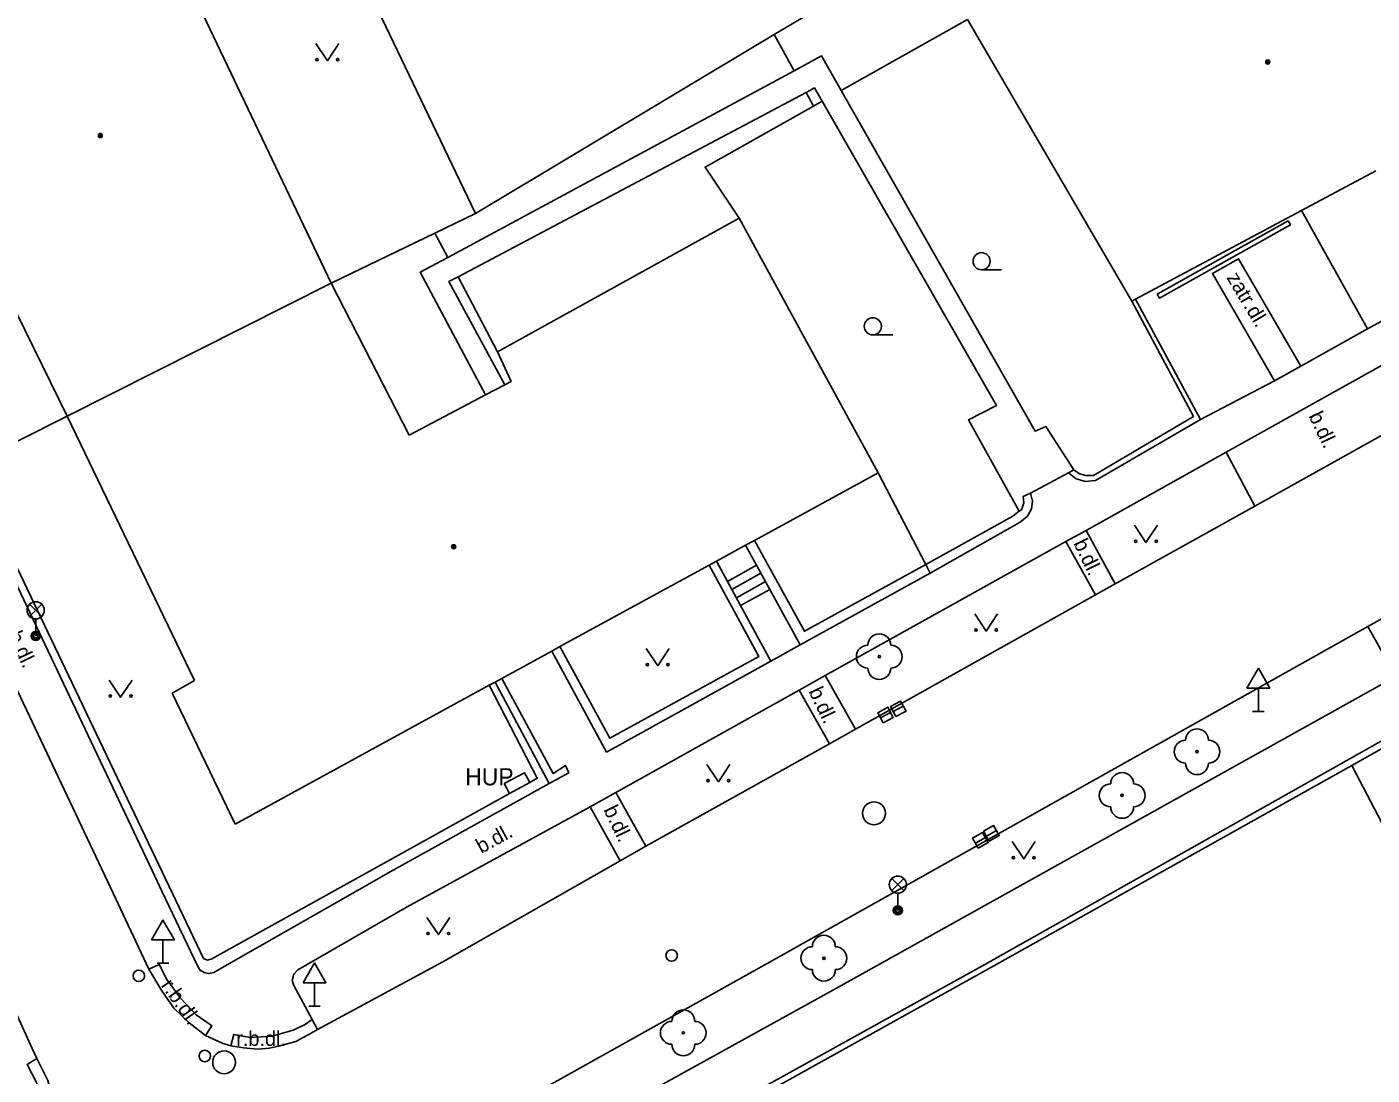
# Model space of a CAD drawing. Extents: x -600391 to -599491, y -1160176 to -1159402.
# Drawn here: x -600164 to -600105.3, y -1159825.7 to -1159779.9 of the extents above; entities that cross this region are included whole.
import ezdxf

# ---------------------------------------------------------------- set-up
doc = ezdxf.new("R2010")
doc.units = 0
for name, color, linetype in [('Level 10', 7, 'Continuous'), ('Level 11', 7, 'Continuous'), ('Level 22', 7, 'Continuous'), ('Level 24', 7, 'Continuous'), ('Level 27', 7, 'Continuous'), ('Level 28', 7, 'Continuous'), ('Level 31', 7, 'Continuous'), ('Level 33', 7, 'Continuous'), ('Level 34', 7, 'Continuous'), ('Level 36', 7, 'Continuous'), ('Level 39', 7, 'Continuous'), ('Level 40', 7, 'Continuous'), ('Level 41', 7, 'Continuous'), ('Level 5', 7, 'Continuous'), ('Level 7', 7, 'Continuous'), ('Level 8', 7, 'Continuous')]:
    doc.layers.add(name, color=color, linetype=linetype)

msp = doc.modelspace()

# ---------------------------------------------------------------- linework, layer by layer
at = {"layer": 'Level 10'}
for points in [[(-600207.08, -1159733.09), (-600204.09, -1159739.42), (-600203.67, -1159740.35), (-600201.73, -1159744.4), (-600201.28, -1159745.31), (-600193.16, -1159762.47), (-600192.72, -1159763.39), (-600190.15, -1159768.81), (-600189.71, -1159769.71), (-600181.16, -1159787.79), (-600180.73, -1159788.7), (-600177.31, -1159795.87), (-600176.88, -1159796.81), (-600175.437, -1159799.852), (-600174.02, -1159802.84), (-600173.59, -1159803.76), (-600165.9, -1159820.02), (-600165.45, -1159820.96), (-600163.81, -1159824.53)], [(-600158.72, -1159821.06), (-600159.95, -1159818.426), (-600160.27, -1159817.74), (-600169.89, -1159797.44), (-600171.51, -1159794.02), (-600173.6, -1159789.61), (-600177.09, -1159782.26), (-600180.56, -1159774.92), (-600184.38, -1159766.92), (-600187.61, -1159760.14), (-600188.03, -1159759.22), (-600189.21, -1159756.74), (-600189.62, -1159755.83), (-600193.78, -1159747.07), (-600194.22, -1159746.13), (-600195.79, -1159742.84), (-600196.2, -1159741.93), (-600197.21, -1159739.84), (-600197.66, -1159738.93), (-600199.99, -1159733.97)], [(-600110.41, -1159800.83), (-600103.41, -1159796.93)], [(-600116.5, -1159804.23), (-600110.41, -1159800.83)], [(-600117.36, -1159804.71), (-600116.5, -1159804.23)], [(-600101.97, -1159804.16), (-600105.46, -1159806.09)], [(-600127.85, -1159810.58), (-600117.36, -1159804.71)], [(-600105.46, -1159806.09), (-600131.34, -1159820.61), (-600140.88, -1159825.93), (-600148.03, -1159829.89)], [(-600128.99, -1159811.21), (-600127.85, -1159810.58)], [(-600137.01, -1159815.69), (-600128.99, -1159811.21)], [(-600138.13, -1159816.32), (-600137.01, -1159815.69)], [(-600151.35, -1159823.7), (-600145.87, -1159820.74), (-600138.13, -1159816.32)], [(-600158.72, -1159821.06), (-600158.15, -1159822.01), (-600157.62, -1159822.76), (-600156.96, -1159823.4), (-600156.24, -1159823.95)], [(-600156.24, -1159823.95), (-600155.7, -1159824.21), (-600155.47, -1159824.3), (-600155.13, -1159824.4)], [(-600155.13, -1159824.4), (-600154.58, -1159824.5), (-600153.96, -1159824.55), (-600153.45, -1159824.51), (-600153, -1159824.4), (-600152.3, -1159824.22), (-600151.63, -1159823.85)], [(-600151.63, -1159823.85), (-600151.35, -1159823.7)], [(-600163.61, -1159824.96), (-600163.81, -1159824.53)], [(-600162.87, -1159828.39), (-600162.83, -1159827.81), (-600162.87, -1159827.03), (-600162.95, -1159826.56), (-600163.13, -1159825.92), (-600163.61, -1159824.96)]]:
    msp.add_lwpolyline(points, dxfattribs=at)
at = {"layer": 'Level 11'}
for points in [[(-600152.97, -1159770.28), (-600144.45, -1159788.06)], [(-600131.4, -1159780.23), (-600124.89, -1159776.37)], [(-600122.96, -1159779.58), (-600128.47, -1159782.68)], [(-600144.45, -1159788.06), (-600131.4, -1159780.23)], [(-600131.4, -1159780.23), (-600130.53, -1159781.82)], [(-600144.01, -1159795.98), (-600146.86, -1159790.62), (-600145.66, -1159789.97), (-600130.53, -1159781.82), (-600129.33, -1159781.17), (-600128.47, -1159782.68), (-600120, -1159797.56), (-600119.53, -1159797.36), (-600118.31, -1159799.25)], [(-600120.7, -1159801.06), (-600122.91, -1159797.06), (-600121.69, -1159796.44), (-600129.31, -1159783.15), (-600129.64, -1159782.57), (-600130.01, -1159782.77), (-600145.21, -1159790.82), (-600145.61, -1159791.03), (-600143.17, -1159795.54)], [(-600130.01, -1159782.77), (-600129.69, -1159783.36)], [(-600129.69, -1159783.36), (-600134.42, -1159786.03), (-600132.93, -1159788.26)], [(-600129.31, -1159783.15), (-600129.69, -1159783.36)], [(-600146.22, -1159788.91), (-600144.45, -1159788.06)], [(-600105.48, -1159793.09), (-600108.36, -1159787.92)], [(-600150.75, -1159791.1), (-600146.22, -1159788.91)], [(-600146.22, -1159788.91), (-600145.66, -1159789.97)], [(-600108.39, -1159794.72), (-600111.11, -1159790.03), (-600112.26, -1159790.67), (-600109.54, -1159795.36)], [(-600145.21, -1159790.82), (-600143.49, -1159794.1)], [(-600103.16, -1159791.82), (-600105.48, -1159793.09)], [(-600105.48, -1159793.09), (-600108.39, -1159794.72)], [(-600111.66, -1159798.48), (-600104.74, -1159794.62)], [(-600108.39, -1159794.72), (-600109.54, -1159795.36)], [(-600109.54, -1159795.36), (-600112.78, -1159797.05)], [(-600117.77, -1159801.9), (-600111.66, -1159798.48)], [(-600111.66, -1159798.48), (-600110.41, -1159800.83)], [(-600126.86, -1159799.38), (-600124.77, -1159803.38)], [(-600129.17, -1159808.23), (-600118.66, -1159802.38)], [(-600118.66, -1159802.38), (-600117.77, -1159801.9)], [(-600118.66, -1159802.38), (-600117.36, -1159804.71)], [(-600116.5, -1159804.23), (-600117.77, -1159801.9)], [(-600133.44, -1159804.12), (-600132.17, -1159803.41)], [(-600124.77, -1159803.38), (-600124.58, -1159803.76)], [(-600133.25, -1159804.48), (-600131.98, -1159803.77)], [(-600133.05, -1159804.84), (-600131.78, -1159804.13)], [(-600132.87, -1159805.18), (-600131.59, -1159804.48)], [(-600105.46, -1159806.09), (-600104.25, -1159808.27)], [(-600104.25, -1159808.27), (-600128.81, -1159821.96), (-600136, -1159825.94), (-600146.47, -1159831.77), (-600146.72, -1159831.81), (-600146.92, -1159831.76), (-600147.11, -1159831.6), (-600147.79, -1159830.34)], [(-600140.37, -1159812.48), (-600140.51, -1159812.17), (-600141.06, -1159812.51), (-600143.3, -1159808.36)], [(-600130.31, -1159808.87), (-600129.17, -1159808.23)], [(-600127.85, -1159810.58), (-600129.17, -1159808.23)], [(-600138.32, -1159813.34), (-600130.31, -1159808.87)], [(-600130.31, -1159808.87), (-600128.99, -1159811.21)], [(-600106.16, -1159812.16), (-600077.12, -1159867.69)], [(-600139.44, -1159813.97), (-600138.32, -1159813.34)], [(-600137.01, -1159815.69), (-600138.32, -1159813.34)], [(-600151.59, -1159823.25), (-600152.38, -1159821.77), (-600152.45, -1159821.56), (-600152.39, -1159821.28), (-600152.21, -1159821.09), (-600147.44, -1159818.34), (-600139.44, -1159813.97)], [(-600139.44, -1159813.97), (-600138.13, -1159816.32)], [(-600158.72, -1159821.06), (-600158.27, -1159820.85), (-600157.93, -1159821.51), (-600157.34, -1159822.33), (-600156.65, -1159823.05), (-600156.08, -1159823.45), (-600155.96, -1159823.53), (-600156.24, -1159823.95)], [(-600151.59, -1159823.25), (-600151.92, -1159823.49), (-600152.42, -1159823.73), (-600153.33, -1159823.99), (-600154.29, -1159824.04), (-600155.01, -1159823.91), (-600155.13, -1159824.4)], [(-600151.35, -1159823.7), (-600151.59, -1159823.25)], [(-600163.61, -1159824.96), (-600164.04, -1159825.22), (-600163.63, -1159826.01), (-600163.35, -1159827.2), (-600163.36, -1159828.31), (-600162.87, -1159828.39)]]:
    msp.add_lwpolyline(points, dxfattribs=at)
at = {"layer": 'Level 22'}
for centre in [(-600126.81, -1159807.41), (-600112.93, -1159811.56), (-600116.2, -1159813.47), (-600129.23, -1159820.58), (-600135.37, -1159823.84)]:
    msp.add_circle(centre, 0.05, dxfattribs=at)
for centre, start, end in [((-600126.81, -1159806.91), 0, 180), ((-600127.31, -1159807.41), 90, 270), ((-600126.31, -1159807.41), 270, 90), ((-600126.81, -1159807.91), 180, 0), ((-600112.93, -1159811.06), 0, 180), ((-600113.43, -1159811.56), 90, 270), ((-600112.43, -1159811.56), 270, 90), ((-600116.2, -1159812.97), 0, 180), ((-600112.93, -1159812.06), 180, 0), ((-600116.7, -1159813.47), 90, 270), ((-600115.7, -1159813.47), 270, 90), ((-600116.2, -1159813.97), 180, 0), ((-600129.73, -1159820.58), 90, 270), ((-600129.23, -1159820.08), 0, 180), ((-600128.73, -1159820.58), 270, 90), ((-600129.23, -1159821.08), 180, 0), ((-600135.37, -1159823.34), 0, 180), ((-600135.87, -1159823.84), 90, 270), ((-600134.87, -1159823.84), 270, 90), ((-600135.37, -1159824.34), 180, 0)]:
    msp.add_arc(centre, 0.5, start, end, dxfattribs=at)
at = {"layer": 'Level 24'}
for points in [[(-600114.67, -1159791.58), (-600108.95, -1159788.38), (-600108.85, -1159788.55), (-600114.57, -1159791.75), (-600114.67, -1159791.58)], [(-600143.19, -1159812.95), (-600142.31, -1159812.48), (-600142.08, -1159812.9)], [(-600142.96, -1159813.39), (-600143.19, -1159812.95)]]:
    msp.add_lwpolyline(points, dxfattribs=at)
at = {"layer": 'Level 27'}
for p, q in [((-600126.761, -1159810.077), (-600126.319, -1159809.843)), ((-600126.201, -1159809.807), (-600125.759, -1159809.573)), ((-600122.609, -1159815.551), (-600122.171, -1159815.309)), ((-600122.129, -1159815.251), (-600121.691, -1159815.009))]:
    msp.add_line(p, q, dxfattribs=at)
for points in [[(-600126.083, -1159810.028), (-600125.642, -1159809.793), (-600125.877, -1159809.352), (-600126.318, -1159809.587)], [(-600126.643, -1159810.298), (-600126.202, -1159810.063), (-600126.437, -1159809.622), (-600126.878, -1159809.857)], [(-600122.007, -1159815.47), (-600121.57, -1159815.227), (-600121.813, -1159814.79), (-600122.25, -1159815.033)], [(-600122.487, -1159815.77), (-600122.05, -1159815.527), (-600122.293, -1159815.09), (-600122.73, -1159815.333)]]:
    msp.add_lwpolyline(points, close=True, dxfattribs=at)
for centre in [(-600127.04, -1159814.25), (-600155.43, -1159825.13)]:
    msp.add_circle(centre, 0.5, dxfattribs=at)
at = {"layer": 'Level 28'}
for centre in [(-600135.88, -1159820.46), (-600156.27, -1159824.85)]:
    msp.add_circle(centre, 0.25, dxfattribs=at)
at = {"layer": 'Level 31'}
msp.add_circle((-600159.16, -1159821.35), 0.25, dxfattribs=at)
at = {"layer": 'Level 33'}
for p, q in [((-600163.925, -1159805.65), (-600163.395, -1159805.12)), ((-600163.925, -1159805.12), (-600163.395, -1159805.65)), ((-600163.66, -1159805.76), (-600163.66, -1159806.51)), ((-600126.265, -1159817.63), (-600125.735, -1159817.1)), ((-600126.265, -1159817.1), (-600125.735, -1159817.63)), ((-600126, -1159817.74), (-600126, -1159818.49))]:
    msp.add_line(p, q, dxfattribs=at)
for centre, radius in [((-600163.66, -1159805.385), 0.375), ((-600163.66, -1159806.51), 0.2), ((-600163.66, -1159806.51), 0.145), ((-600163.66, -1159806.51), 0.0876), ((-600126, -1159817.365), 0.375), ((-600126, -1159818.49), 0.2), ((-600126, -1159818.49), 0.145), ((-600126, -1159818.49), 0.0876)]:
    msp.add_circle(centre, radius, dxfattribs=at)
at = {"layer": 'Level 34'}
for p, q in [((-600110.25, -1159808.782), (-600110.25, -1159809.8)), ((-600110.5, -1159809.8), (-600110, -1159809.8)), ((-600158.1, -1159819.782), (-600158.1, -1159820.8)), ((-600158.35, -1159820.8), (-600157.85, -1159820.8)), ((-600151.48, -1159821.652), (-600151.48, -1159822.67)), ((-600151.73, -1159822.67), (-600151.23, -1159822.67))]:
    msp.add_line(p, q, dxfattribs=at)
for points in [[(-600110.75, -1159808.782), (-600109.75, -1159808.782), (-600110.25, -1159807.916)], [(-600158.6, -1159819.782), (-600157.6, -1159819.782), (-600158.1, -1159818.916)], [(-600151.98, -1159821.652), (-600150.98, -1159821.652), (-600151.48, -1159820.786)]]:
    msp.add_lwpolyline(points, close=True, dxfattribs=at)
at = {"layer": 'Level 36'}
for p, q in [((-600122.34, -1159790.515), (-600121.465, -1159790.515)), ((-600127.09, -1159793.355), (-600126.215, -1159793.355))]:
    msp.add_line(p, q, dxfattribs=at)
for points in [[(-600151.42, -1159780.63), (-600150.92, -1159781.38), (-600150.42, -1159780.63)], [(-600115.66, -1159801.67), (-600115.16, -1159802.42), (-600114.66, -1159801.67)], [(-600122.64, -1159805.54), (-600122.14, -1159806.29), (-600121.64, -1159805.54)], [(-600136.99, -1159807.06), (-600136.49, -1159807.81), (-600135.99, -1159807.06)], [(-600160.45, -1159808.43), (-600159.95, -1159809.18), (-600159.45, -1159808.43)], [(-600134.34, -1159812.12), (-600133.84, -1159812.87), (-600133.34, -1159812.12)], [(-600121, -1159815.49), (-600120.5, -1159816.24), (-600120, -1159815.49)], [(-600146.57, -1159818.8), (-600146.07, -1159819.55), (-600145.57, -1159818.8)]]:
    msp.add_lwpolyline(points, dxfattribs=at)
for centre, radius in [((-600151.37, -1159781.33), 0.05), ((-600150.471, -1159781.33), 0.05), ((-600122.34, -1159790.14), 0.375), ((-600127.09, -1159792.98), 0.375), ((-600115.61, -1159802.37), 0.05), ((-600114.711, -1159802.37), 0.05), ((-600122.59, -1159806.24), 0.05), ((-600121.691, -1159806.24), 0.05), ((-600136.94, -1159807.76), 0.05), ((-600136.041, -1159807.76), 0.05), ((-600160.4, -1159809.13), 0.05), ((-600159.501, -1159809.13), 0.05), ((-600134.29, -1159812.82), 0.05), ((-600133.391, -1159812.82), 0.05), ((-600120.95, -1159816.19), 0.05), ((-600120.051, -1159816.19), 0.05), ((-600146.52, -1159819.5), 0.05), ((-600145.621, -1159819.5), 0.05)]:
    msp.add_circle(centre, radius, dxfattribs=at)
at = {"layer": 'Level 39'}
for centre, radius in [((-600109.84, -1159781.44), 0.09), ((-600109.84, -1159781.44), 0.0398), ((-600160.84, -1159784.65), 0.09), ((-600160.84, -1159784.65), 0.0398), ((-600145.4, -1159802.61), 0.09), ((-600145.4, -1159802.61), 0.0398)]:
    msp.add_circle(centre, radius, dxfattribs=at)
at = {"layer": 'Level 5'}
for points in [[(-600159.23, -1159773.32), (-600150.75, -1159791.1)], [(-600115.78, -1159791.88), (-600122.96, -1159779.58)], [(-600105.12, -1159786.19), (-600108.36, -1159787.92)], [(-600143.49, -1159794.1), (-600132.93, -1159788.26)], [(-600132.93, -1159788.26), (-600126.86, -1159799.38)], [(-600108.36, -1159787.92), (-600115.62, -1159791.79)], [(-600162.28, -1159796.91), (-600165.23, -1159790.93)], [(-600150.75, -1159791.1), (-600162.28, -1159796.91)], [(-600150.75, -1159791.1), (-600147.35, -1159797.74)], [(-600115.62, -1159791.79), (-600115.78, -1159791.88)], [(-600142.89, -1159795.39), (-600143.49, -1159794.1)], [(-600147.35, -1159797.74), (-600144.01, -1159795.98), (-600143.17, -1159795.54), (-600142.89, -1159795.39)], [(-600156.72, -1159808.45), (-600162.28, -1159796.91)], [(-600126.86, -1159799.38), (-600132.26, -1159802.33)], [(-600132.26, -1159802.33), (-600132.65, -1159802.54)], [(-600132.65, -1159802.54), (-600133.92, -1159803.24)], [(-600134.24, -1159803.41), (-600140.76, -1159806.97)], [(-600133.92, -1159803.24), (-600134.24, -1159803.41)], [(-600141.11, -1159807.17), (-600143.3, -1159808.36), (-600143.59, -1159808.52)], [(-600140.76, -1159806.97), (-600141.11, -1159807.17)], [(-600157.7, -1159809.01), (-600156.72, -1159808.45)], [(-600143.85, -1159808.66), (-600154.94, -1159814.73)], [(-600143.59, -1159808.52), (-600143.85, -1159808.66)], [(-600154.94, -1159814.73), (-600157.7, -1159809.01)]]:
    msp.add_lwpolyline(points, dxfattribs=at)
at = {"layer": 'Level 7'}
for points in [[(-600115.78, -1159791.88), (-600113.08, -1159796.92), (-600117.45, -1159799.5), (-600117.79, -1159799.5), (-600118.06, -1159799.42), (-600118.31, -1159799.25), (-600118.54, -1159799.38)], [(-600115.62, -1159791.79), (-600112.78, -1159797.05)], [(-600166.61, -1159799.07), (-600162.28, -1159796.91)], [(-600112.78, -1159797.05), (-600117.36, -1159799.72), (-600117.8, -1159799.76), (-600118.21, -1159799.64), (-600118.54, -1159799.38)], [(-600155.88, -1159821.2), (-600156.11, -1159821.25), (-600156.3, -1159821.21), (-600156.47, -1159821.1), (-600156.58, -1159820.94), (-600158.15, -1159817.65), (-600158.58, -1159816.75), (-600166.59, -1159799.86), (-600166.9, -1159799.22)], [(-600143.85, -1159808.66), (-600141.75, -1159812.72), (-600142.08, -1159812.9), (-600142.96, -1159813.39), (-600155.97, -1159820.61), (-600156.16, -1159820.67), (-600156.33, -1159820.59), (-600166.61, -1159799.07)], [(-600120.2, -1159800.27), (-600120.52, -1159800.41), (-600120.49, -1159800.69), (-600120.6, -1159800.99), (-600120.7, -1159801.06), (-600120.98, -1159801.27), (-600124.77, -1159803.38)], [(-600120.2, -1159800.27), (-600120.12, -1159800.62), (-600120.16, -1159800.95), (-600120.33, -1159801.27), (-600120.66, -1159801.54), (-600124.58, -1159803.76)], [(-600124.77, -1159803.38), (-600130.08, -1159806.3), (-600132.26, -1159802.33)], [(-600132.65, -1159802.54), (-600132.17, -1159803.41)], [(-600134.24, -1159803.41), (-600132.07, -1159807.4), (-600138.58, -1159810.97), (-600140.76, -1159806.97)], [(-600133.92, -1159803.24), (-600133.44, -1159804.12)], [(-600132.17, -1159803.41), (-600131.59, -1159804.48)], [(-600133.44, -1159804.12), (-600132.87, -1159805.18)], [(-600124.58, -1159803.76), (-600130.27, -1159806.89)], [(-600131.59, -1159804.48), (-600130.27, -1159806.89)], [(-600132.87, -1159805.18), (-600131.54, -1159807.61)], [(-600141.11, -1159807.17), (-600138.73, -1159811.58)], [(-600131.54, -1159807.61), (-600138.73, -1159811.58)], [(-600143.59, -1159808.52), (-600141.23, -1159812.95)], [(-600149.41, -1159835.92), (-600144.23, -1159833.05), (-600122.2, -1159820.86), (-600103.21, -1159810.15)], [(-600149.28, -1159836.18), (-600144.11, -1159833.31), (-600122.04, -1159821.05), (-600106.16, -1159812.16), (-600103.06, -1159810.42)], [(-600141.23, -1159812.95), (-600148.04, -1159816.73), (-600155.33, -1159820.88), (-600155.88, -1159821.2)], [(-600141.23, -1159812.95), (-600140.37, -1159812.48)]]:
    msp.add_lwpolyline(points, dxfattribs=at)
at = {"layer": 'Level 8'}
for points in [[(-600120.2, -1159800.27), (-600118.54, -1159799.38)], [(-600131.54, -1159807.61), (-600130.27, -1159806.89)]]:
    msp.add_lwpolyline(points, dxfattribs=at)

# ---------------------------------------------------------------- texts
at = {"layer": 'Level 40'}
for s, rotation, p in [('zatr.dl.', 300.9, (-600111.66, -1159790.85)), ('b.dl. ', 295.57, (-600108.07, -1159796.89)), ('b.dl. ', 295.57, (-600118.34, -1159802.45)), ('b.dl. ', 295.37, (-600164.89, -1159806.48)), ('b.dl. ', 295.57, (-600129.91, -1159808.92)), ('b.dl. ', 295.57, (-600138.87, -1159814.09)), ('b.dl. ', 28.69, (-600144.2, -1159816.03)), ('r.b.dl.', 305, (-600158.21, -1159821.77))]:
    msp.add_text(s, height=0.65, rotation=rotation, dxfattribs=at).set_placement(p)
msp.add_text('r.b.dl.', height=0.65, dxfattribs=at).set_placement((-600154.9, -1159824.41))
at = {"layer": 'Level 41'}
msp.add_text('HUP', height=0.75, dxfattribs=at).set_placement((-600144.9, -1159813.03))
msp.add_text('HUP', height=0.75, dxfattribs=at).set_placement((-600144.9, -1159813.03))

doc.saveas('drawing.dxf')
